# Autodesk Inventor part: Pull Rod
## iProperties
Shininess: 64.0
Angle Display Precision: 2
Document Length Units: 11269
Document Angle Units: 11279
Document Time Units: 11290
Document Mass Units: 11283
Document Length Units Precision: 3
Document Angle Units Precision: 2
Compacted: True
Created: 2001-09
Part Number: Pull Rod
Document SubType Name: Modeling
Designer: Martin Budgell
Density: 0.0
Volumn: 0.0
Area: 0.0
PropertySet Name: Model Information
Control State: 0
Master: False
Checked Out: False
Author: Martin Budgell
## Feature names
1. Extrusion1
